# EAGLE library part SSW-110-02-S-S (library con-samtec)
THROUGH-HOLE .025" SQ POST SOCKET Source: Samtec SSW.pdf
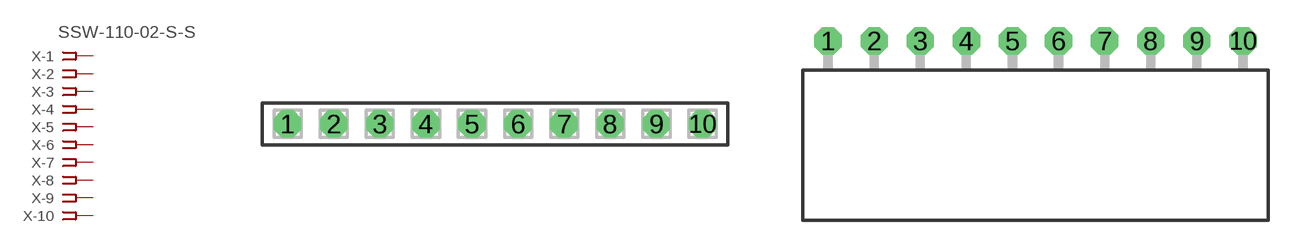
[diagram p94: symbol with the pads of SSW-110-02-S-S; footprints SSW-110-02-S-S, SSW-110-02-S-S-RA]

Designator prefix X; gates -1=FPINV -2=FPIN -3=FPIN -4=FPIN -5=FPIN -6=FPIN -7=FPIN -8=FPIN -9=FPIN -10=FPIN

## SSW-110-02-S-S (MPN: SSW-110-02-S-S; OC_FARNELL: unknown; OC_NEWARK: 11P9482)  [SSW-110-02-S-S]
1  -1:1  pas
2  -2:1  pas
3  -3:1  pas
4  -4:1  pas
5  -5:1  pas
6  -6:1  pas
7  -7:1  pas
8  -8:1  pas
9  -9:1  pas
10  -10:1  pas

## SSW-110-02-S-S-RA (MPN: SSW-110-02-S-S-RA; OC_FARNELL: unknown; OC_NEWARK: 11P9483)  [SSW-110-02-S-S-RA]
Pads as for SSW-110-02-S-S

## Footprint SSW-110-02-S-S (pad centres in mm)
THROUGH-HOLE .025" SQ POST SOCKET Source: Samtec SSW.pdf
drill 1 pad 1.5 octagon: 1 -11.43,0; 2 -8.89,0; 3 -6.35,0; 4 -3.81,0; 5 -1.27,0; 6 1.27,0; 7 3.81,0; 8 6.35,0; 9 8.89,0; 10 11.43,0

## Footprint SSW-110-02-S-S-RA (pad centres in mm)
THROUGH-HOLE .025" SQ POST SOCKET Source: Samtec SSW.pdf
drill 1 pad 1.5 octagon: 1 -11.43,1.524; 2 -8.89,1.524; 3 -6.35,1.524; 4 -3.81,1.524; 5 -1.27,1.524; 6 1.27,1.524; 7 3.81,1.524; 8 6.35,1.524; 9 8.89,1.524; 10 11.43,1.524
